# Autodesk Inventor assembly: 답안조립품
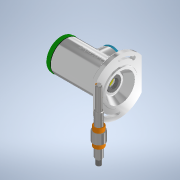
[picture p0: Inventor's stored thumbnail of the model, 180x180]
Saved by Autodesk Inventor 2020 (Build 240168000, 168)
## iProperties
Created: 2022-05
Part Number: 답안조립품
Document SubType Name: Assembly
Designer: Student
Author: Student
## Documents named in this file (15)
- C:\Users\Student\Desktop\720506V1022\답안조립품.iam
- C:\Users\Student\Desktop\720506V1022\본체.ipt
- C:\Users\Student\Desktop\720506V1022\베어링 6202.ipt
- C:\Users\Student\Desktop\720506V1022\탑 커버.ipt
- C:\Users\Student\Desktop\720506V1022\와셔 3 x 6.ipt
- C:\Users\Student\Desktop\720506V1022\십자볼트 M3 x 10.ipt
- C:\Users\Student\Desktop\720506V1022\사이드 커버.ipt
- 사이드 커버.ipt
- C:\Users\Student\Desktop\720506V1022\축.ipt
- C:\Users\Student\Desktop\720506V1022\멈춤링 35 x 1.6.ipt
- C:\Users\Student\Desktop\720506V1022\오일 실 15 x 30 x 7.ipt
- C:\Users\Student\Desktop\720506V1022\개스킷.ipt
- C:\Users\Student\Desktop\720506V1022\키 4 x 4.ipt
- C:\Users\Student\Desktop\720506V1022\부시1.ipt
- C:\Users\Student\Desktop\720506V1022\볼트 M4 x 10.ipt
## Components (2 placed, 2 different names)
1. 개스킷:1
2. ISO 4017 M4 x 10:1
